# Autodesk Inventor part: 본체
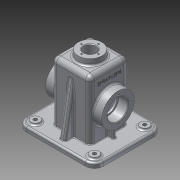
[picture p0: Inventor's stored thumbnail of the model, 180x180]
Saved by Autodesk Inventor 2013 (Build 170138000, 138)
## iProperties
Created: 2016-06
Part Number: 본체
Material: 알루미늄 6061
Document SubType Name: Modeling
Designer: k
Density: 2.71 g/cm^3
Mass: 806.269 g
Surface Area: 909.624 cm^2
Volume: 297.516 cm^3
Author: k
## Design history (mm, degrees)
sketch "스케치1"
  geometry: L1 (-32.5, 32.5)-(32.5, 32.5); L2 (32.5, 32.5)-(32.5, -32.5); L3 (32.5, -32.5)-(-32.5, -32.5); L4 (-32.5, -32.5)-(-32.5, 32.5); 2 further points
  constraints: 8 end point, 2 parallel, 1 coincident, 1 horizontal, 1 perpendicular
  dimensions: "d0" = 65 distance of L2.end L3.end; "d1" = 65 distance of L1.end L2.end
extrude "돌출1" new body sketch "스케치1" distance "d2" = 110; taper "d3" = 0 deg
sketch "스케치2"
  geometry: L1 (-65, 57.5)-(65, 57.5); L2 (65, 57.5)-(65, -57.5); L3 (65, -57.5)-(-65, -57.5); L4 (-65, -57.5)-(-65, 57.5); L5 (-65, 57.5)-(65, -57.5); L6 (65, 57.5)-(-65, -57.5); 1 further point
  constraints: 12 end point, 2 midpoint, 2 parallel, 1 horizontal, 1 perpendicular
  dimensions: "d4" = 130 distance of L2.end L3.end; "d5" = 115 distance of L1.end L2.end
extrude "돌출2" join sketch "스케치2" distance "d6" = 10; taper "d7" = 0 deg
feature "쉘1" dims "d8" = 12, "d9" = 5
sketch "스케치4"
  geometry: L1 (-110, -25)-(-110, 90) reference; C1 r 27.5 at (-55, 32.5); 2 further points
  constraints: 1 centre point, 1 horizontal alignment, 1 midpoint
  dimensions: "d22" = 55 diameter of C1; "d24" = 55 distance from line of C1.centre L1
fillet "모깎기1" dims "d25" = 8
fillet "모깎기2" dims "d26" = 8
extrude "돌출4" join sketch "스케치4" distance "d27" = 15; taper "d28" = 0 deg
fillet "모깎기3" dims "d29" = 15
node "작업 평면1"
sketch "스케치5"
  geometry: C1 r 20 at (0, 0); 1 further point
  constraints: 1 centre point, 1 coincident
  dimensions: "d31" = 40 diameter of C1
extrude "돌출5" join sketch "스케치5" distance "d32" = 15; taper "d33" = 5 deg
sketch "스케치6"
  geometry: L1 (27.5, 0)-(27.5, 105) reference; L2 (27.5, 105)-(-27.5, 105) reference; L3 (-27.5, 105)-(-27.5, 0) reference; L4 (-27.5, 0)-(-57.5, 0) reference; L5 (-57.5, 0)-(-57.5, 10) reference; L6 (-57.5, 10)-(-32.5, 10) reference; L7 (-32.5, 10)-(-32.5, 102) reference; L8 (-24.5, 110)-(-20.875, 110) reference; L9 (-20.875, 110)-(-20, 120) reference; L10 (-20, 120)-(20, 120) reference; L11 (20, 120)-(20.875, 110) reference; L12 (20.875, 110)-(24.5, 110) reference; L13 (32.5, 102)-(32.5, 10) reference; L14 (32.5, 10)-(57.5, 10) reference; L15 (57.5, 10)-(57.5, 0) reference; L16 (57.5, 0)-(27.5, 0) reference; L17 (47.5, 10)-(32.5, 95.069); A1 r 8 centre (-24.5, 102) between (-24.5, 110) and (-32.5, 102) reference; A2 r 8 centre (24.5, 102) between (32.5, 102) and (24.5, 110) reference; 1 further point
  constraints: 2 end point, 2 point on line
  dimensions: "d34" = 10 distance from line of L15 L17.start; "d35" = 10 deg angle of L15 L17
feature "리브1" sketch "스케치6" dims "d36" = 1, "d37" = 10, "d38" = 0, "d39" = 0, "d40" = 1, "d41" = 1
sketch "스케치7"
  geometry: L1 (-42.5, 12)-(-42.5, 27.5); L2 (-27.5, 0)-(-27.5, 105) reference; 1 further point
  constraints: 2 end point, 1 vertical
  dimensions: "d42" = 15 distance between parallel lines of L1 L2
feature "리브2" sketch "스케치7" dims "d43" = 1, "d44" = 6, "d45" = 0, "d46" = 0, "d47" = 1, "d48" = 1
hole "구멍2" diameter "d51" = 21; stored, may be unused: countersink angle "d55" = 90 deg, drill point angle "d57" = 118 deg; dims "d49" = 10, "d50" = 10, "d52" = 6, "d53" = 35, "d54" = 17, "d56" = 8
hole "구멍3" diameter "d60" = 30; stored, may be unused: countersink angle "d64" = 90 deg, drill point angle "d66" = 118 deg; dims "d58" = 10, "d59" = 10, "d61" = 6, "d62" = 35, "d63" = 17, "d65" = 8
sketch "스케치8"
  geometry: L1 (-65, 42.5)-(-65, -42.5) reference; L2 (-50, -57.5)-(50, -57.5) reference; L3 (65, -42.5)-(65, 42.5) reference; L4 (50, 57.5)-(-50, 57.5) reference; L5 (-50, 52.5)-(50, 52.5); L6 (60, 42.5)-(60, -42.5); L7 (50, -52.5)-(-50, -52.5); L8 (-60, -42.5)-(-60, 42.5); A1 r 15 centre (-50, -42.5) between (-65, -42.5) and (-50, -57.5) reference; A2 r 15 centre (50, -42.5) between (50, -57.5) and (65, -42.5) reference; A3 r 15 centre (50, 42.5) between (65, 42.5) and (50, 57.5) reference; A4 r 15 centre (-50, 42.5) between (-50, 57.5) and (-65, 42.5) reference; A5 r 10 centre (50, 42.5) between (60, 42.5) and (50, 52.5); A6 r 10 centre (50, -42.5) between (50, -52.5) and (60, -42.5); A7 r 10 centre (-50, -42.5) between (-60, -42.5) and (-50, -52.5); A8 r 10 centre (-50, 42.5) between (-50, 52.5) and (-60, 42.5); 1 further point
  constraints: 8 end point, 8 point on circle, 4 centre point, 7 other
  dimensions: "d67" = 5 distance between parallel lines of L5 L4
extrude "돌출6" cut sketch "스케치8" distance "d68" = 2; taper "d69" = 0 deg
sketch "스케치9"
  geometry: C1 r 7.5 at (-50, 42.5); C2 r 7.5 at (50, 42.5); C3 r 7.5 at (50, -42.5); C4 r 7.5 at (-50, -42.5); A1 r 15 centre (50, 42.5) between (65, 42.5) and (50, 57.5) reference; A2 r 15 centre (-50, 42.5) between (-50, 57.5) and (-65, 42.5) reference; A3 r 15 centre (-50, -42.5) between (-65, -42.5) and (-50, -57.5) reference; A4 r 15 centre (50, -42.5) between (50, -57.5) and (65, -42.5) reference; 1 further point
  constraints: 4 centre point, 4 coincident, 2 equal radius, 1 vertical alignment
  dimensions: "d70" = 15 diameter of C1; "d71" = 15 diameter of C4
extrude "돌출7" join sketch "스케치9" distance "d72" = 3; taper "d73" = 0 deg
hole "구멍4" diameter "d76" = 6; stored, may be unused: countersink angle "d80" = 90 deg, drill point angle "d82" = 118 deg; dims "d74" = 10, "d75" = 10, "d77" = 6, "d78" = 35, "d79" = 17, "d81" = 8
hole "구멍5" diameter "d85" = 6; stored, may be unused: countersink angle "d89" = 90 deg, drill point angle "d91" = 118 deg; dims "d83" = 10, "d84" = 10, "d86" = 6, "d87" = 35, "d88" = 17, "d90" = 8
hole "구멍6" diameter "d94" = 6; stored, may be unused: countersink angle "d98" = 90 deg, drill point angle "d100" = 118 deg; dims "d92" = 10, "d93" = 10, "d95" = 6, "d96" = 35, "d97" = 17, "d99" = 8
hole "구멍7" diameter "d103" = 6; stored, may be unused: countersink angle "d107" = 90 deg, drill point angle "d109" = 118 deg; dims "d101" = 10, "d102" = 10, "d104" = 6, "d105" = 35, "d106" = 17, "d108" = 8
fillet "모깎기4" dims "d110" = 3
fillet "모깎기5" dims "d111" = 3
fillet "모깎기6" dims "d112" = 3
fillet "모깎기7" dims "d113" = 3
fillet "모깎기8" dims "d114" = 3
fillet "모깎기9" dims "d115" = 3
fillet "모깎기10" dims "d116" = 3
fillet "모깎기11" dims "d117" = 3
fillet "모깎기12" dims "d118" = 3
fillet "모깎기13" dims "d119" = 3
fillet "모깎기14" dims "d120" = 3
sketch "스케치10"
  geometry: C1 r 17.5 at (0, 0) reference; 2 further points
  constraints: 1 horizontal alignment
  dimensions: "d121" = 21 distance of point (-21, 0) C1.centre
hole "구멍8" sketch "스케치10" at (-21, 0) diameter "d122" = 3.242; stored, may be unused: countersink angle "d126" = 90 deg, drill point angle "d128" = 118 deg; dims "d123" = 8, "d124" = 35, "d125" = 17, "d127" = 10
fillet "모깎기15" dims "d132" = 1
sketch "스케치11"
  geometry: C1 r 10.5 at (0, 0) reference; 1 further point
  constraints: 1 vertical alignment
  dimensions: "d133" = 14.5 distance of point (0, 14.5) C1.centre
hole "구멍9" sketch "스케치11" at (0, 14.5) diameter "d134" = 2.459; stored, may be unused: countersink angle "d138" = 90 deg, drill point angle "d140" = 118 deg; dims "d135" = 7, "d136" = 35, "d137" = 17, "d139" = 9
fillet "모깎기16" dims "d144" = 0.3
fillet "모깎기17" dims "d145" = 0.3
fillet "모깎기18" dims "d146" = 3
chamfer "모따기1" distance "d147" = 1; stored, may be unused: second distance "d148" = 2, angle "d149" = 45 deg
chamfer "모따기2" distance "d150" = 1; stored, may be unused: second distance "d151" = 2, angle "d152" = 45 deg
fillet "모깎기19" dims "d153" = 3
fillet "모깎기20" dims "d154" = 3
sketch "스케치12"
  geometry: L1 (-18, 4.5)-(-18, 44.5) reference; L2 (0, -8)-(91, -8) reference; 1 further point
  constraints: 1 other
  dimensions: "d155" = 26 distance from line of point (8, 24.5) L1; "d156" = 32.5 distance from line of point (8, 24.5) L2
feature "엠보싱1" sketch "스케치12" dims "d157" = 0.5, "d158" = 0
node "솔리드1"
mirror "대칭1"
mirror "대칭2"
mirror "대칭3"
mirror "대칭4"
pattern_circular "원형 패턴1" dims angle "d130" = 360 deg
mirror "대칭5"
pattern_circular "원형 패턴2" dims angle "d142" = 360 deg
node "절단 모서리 투영1"
